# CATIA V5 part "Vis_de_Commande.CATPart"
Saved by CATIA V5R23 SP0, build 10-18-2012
Part number: Vis_de_Commande
Material "Acier": density 7860 kg/m3, Young's modulus 2e+11 Pa, Poisson ratio 0.266, thermal expansion 1.17e-05 1/K
Bounding box of the stored display mesh (mm): x -6 to 6, y -5.956 to 5.956, z -34 to 161
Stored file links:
  P:\eleve\Vis_de_Commande.CATPart
  d:\catia_soft\intel_a\reffiles\standard\MetricThickPitch.txt
  C:\Program Files\Dassault Systemes\B23\win_b64\startup\materials\French\Catalog.CATMaterial
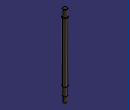
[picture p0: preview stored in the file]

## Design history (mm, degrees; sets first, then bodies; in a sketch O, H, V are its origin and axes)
Body1 (main body)
  Sketch1 on xy-plane, origin (0, 0, 0), H (1, 0, 0), V (0, 1, 0)
    circle A1 centre (0, 0) radius 6
    radius A1 = 6
  Pad1: profile Sketch1, direction (0, 0, 1), length 144
  Sketch2 on face of Pad1, origin (0, 0, 144), H (1, 0, 0), V (0, 1, 0)
    circle A1 centre (0, 0) radius 5
    radius A1 = 5
  Pad2: profile Sketch2, direction (0, 0, 1), length 17
  Thread1: diameter 12, depth 144, pitch 1.25, on face of Pad1, from face of Pad1
  Sketch3 on face of Pad1, origin (0, 0, 0), H (1, 0, 0), V (0, -1, 0)
    circle A1 centre (0, 0) radius 5
    radius A1 = 5
  Pad3: profile Sketch3, direction (0, 0, -1), length 20
  Chamfer1: length 0.5, angle 45, on edge [face of Pad1 | face of Pad1] (x2); edge [face of Pad2 | face of Pad2]
  Sketch4 on face of Pad3, origin (0, 0, -20), H (1, 0, 0), V (0, -1, 0)
    circle A1 centre (0, 0) radius 4
    point P1 (4, 0)
    radius A1 = 4
    coincidence: A1 P1, P1 H
  Pad4: profile Sketch4, direction (0, 0, -1), length 14
  Sketch5 on face of Pad4, origin (0, 0, -34), H (1, 0, 0), V (0, -1, 0)
    line L1 (-8, 8) -> (8, 8)
    line L2 (8, 8) -> (8, 3)
    line L3 (8, 3) -> (-8, 3)
    line L4 (-8, 3) -> (-8, 8)
    reference projected point E1 (0, 0) from axis of face of Pad4
    distance L3 E1 = 3
    distance L1 H = 8
    distance L4 V = 8
    horizontal: L1 H, L3 H
    vertical: L2 V, L4 V
    symmetry: L4 L2 V
  Pocket1: profile Sketch5, direction (0, 0, 1), length 12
